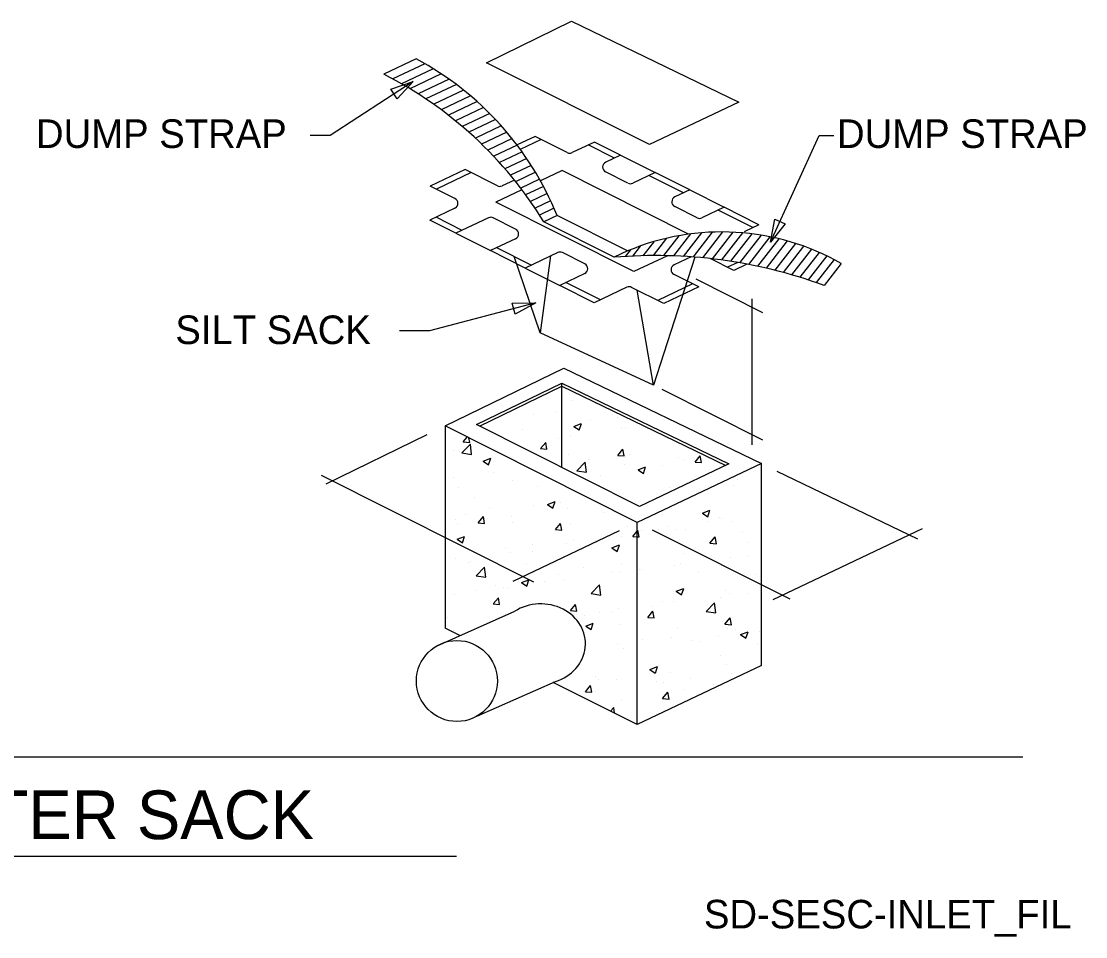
# Model space of a CAD drawing. Extents: x 10109 to 10183.6, y 10015.3 to 10070.3.
# Drawn here: x 10144.72 to 10183.58, y 10015.27 to 10048.68 of the extents above; entities that cross this region are included whole.
import ezdxf

# ---------------------------------------------------------------- set-up
doc = ezdxf.new("R2010")
doc.units = 0
for name, color, linetype in [('Default', 7, 'Continuous'), ('G-ANNO-TEXT', 7, 'Continuous'), ('G-DETL-LINE', 7, 'Continuous'), ('G-DETL-OTLN', 7, 'Continuous'), ('G-DETL-PATT', 7, 'Continuous')]:
    doc.layers.add(name, color=color, linetype=linetype)

# ---------------------------------------------------------------- blocks, each defined once
blk = doc.blocks.new('TERARR')
at = {"layer": 'Default'}
blk.add_lwpolyline([(-0.667, 0.167), (0, 0), (-0.667, -0.167)], close=True, dxfattribs=at)

msp = doc.modelspace()

# ---------------------------------------------------------------- linework, layer by layer
at = {"layer": 'Default'}
for p, q in [((10165.479, 10034.849), (10165.479, 10034.849)), ((10165.702, 10034.715), (10165.702, 10034.715)), ((10164.459, 10032.544), (10164.459, 10032.544)), ((10167.043, 10029.878), (10167.205, 10030.07)), ((10167.205, 10030.07), (10167.233, 10030.103)), ((10167.043, 10029.878), (10167.205, 10029.863)), ((10164.564, 10028.293), (10164.564, 10028.293)), ((10171.674, 10026.421), (10171.674, 10026.421)), ((10165.311, 10026.216), (10165.311, 10026.216)), ((10168.378, 10023.586), (10168.378, 10023.586))]:
    msp.add_line(p, q, dxfattribs=at)
at = {"layer": 'G-ANNO-TEXT'}
for p, q in [((10171.795, 10038.037), (10169.364, 10039.259)), ((10171.408, 10033.218), (10171.408, 10038.547)), ((10163.503, 10038.399), (10159.618, 10037.374)), ((10159.618, 10037.374), (10158.533, 10037.374)), ((10171.795, 10033.388), (10168.12, 10035.235)), ((10155.851, 10031.801), (10159.543, 10033.595)), ((10172.308, 10032.262), (10177.435, 10029.787)), ((10163.427, 10028.205), (10155.687, 10032.094)), ((10166.55, 10030.074), (10162.669, 10028.232)), ((10172.784, 10027.58), (10167.761, 10030.105)), ((10177.609, 10030.155), (10172.153, 10027.567)), ((10129.979, 10018.209), (10160.613, 10018.209))]:
    msp.add_line(p, q, dxfattribs=at)
for points in [[(10159.023, 10046.482), (10156.001, 10044.51), (10155.262, 10044.51)], [(10172.072, 10040.612), (10173.85, 10044.504), (10174.388, 10044.504)]]:
    msp.add_lwpolyline(points, dxfattribs=at)
at = {"layer": 'G-DETL-LINE'}
for p, q in [((10161.704, 10047.166), (10164.813, 10048.676)), ((10164.813, 10048.676), (10170.919, 10045.728)), ((10159.142, 10047.305), (10157.955, 10046.742)), ((10167.65, 10044.177), (10161.704, 10047.166)), ((10170.919, 10045.728), (10167.65, 10044.177)), ((10163.702, 10044.363), (10162.939, 10044.001)), ((10166.373, 10043.684), (10165.42, 10044.163)), ((10161.15, 10043.152), (10159.874, 10042.547)), ((10168.897, 10042.415), (10167.635, 10043.05)), ((10164.281, 10041.586), (10163.795, 10041.355)), ((10166.854, 10040.293), (10164.281, 10041.586)), ((10171.422, 10041.147), (10170.159, 10041.781)), ((10160.815, 10041.047), (10159.863, 10041.526)), ((10166.368, 10040.062), (10163.795, 10041.355)), ((10163.34, 10039.779), (10162.078, 10040.413)), ((10163.666, 10037.309), (10162.717, 10040.092)), ((10164.044, 10040.113), (10163.666, 10037.309)), ((10166.854, 10040.293), (10166.368, 10040.062)), ((10169.309, 10040.069), (10167.799, 10035.397)), ((10170.878, 10039.873), (10170.506, 10039.697)), ((10174.657, 10039.839), (10174.033, 10039.034)), ((10165.864, 10038.51), (10164.602, 10039.145)), ((10167.799, 10035.397), (10167.203, 10038.864)), ((10169.23, 10039.092), (10167.954, 10038.486)), ((10167.799, 10035.397), (10163.666, 10037.309)), ((10161.341, 10033.958), (10164.45, 10035.469)), ((10161.451, 10033.902), (10164.45, 10035.36)), ((10164.45, 10035.36), (10164.45, 10035.469)), ((10164.45, 10035.469), (10170.556, 10032.521)), ((10164.45, 10032.395), (10164.45, 10035.36)), ((10164.45, 10035.36), (10170.442, 10032.467)), ((10167.287, 10030.97), (10161.341, 10033.958)), ((10170.556, 10032.521), (10167.287, 10030.97)), ((10159.901, 10025.888), (10162.736, 10027.142)), ((10161.35, 10023.311), (10164.219, 10024.579)), ((10108.968, 10021.831), (10181.284, 10021.831))]:
    msp.add_line(p, q, dxfattribs=at)
for centre, radius, start, end in [((10153.816, 10037.35), 11.289, 22.0339, 61.8533), ((10151.414, 10033.791), 14.509, 31.4237, 63.2038), ((10170.294, 10032.133), 8.856, 60.4856, 112.8629), ((10167.881, 10022.259), 17.868, 69.8606, 94.8587)]:
    msp.add_arc(centre, radius, start, end, dxfattribs=at)
msp.add_ellipse((10163.686, 10025.957), major_axis=(1.631, 0), ratio=0.894176, start_param=5.045139, end_param=8.475957, dxfattribs=at)
at = {"layer": 'G-DETL-OTLN'}
for p, q in [((10163.479, 10044.475), (10162.819, 10044.162)), ((10164.655, 10043.884), (10163.479, 10044.475)), ((10165.645, 10044.27), (10164.828, 10043.882)), ((10166.598, 10043.791), (10165.645, 10044.27)), ((10166.598, 10043.791), (10166.058, 10043.534)), ((10166.598, 10043.791), (10167.86, 10043.156)), ((10160.927, 10043.264), (10159.651, 10042.659)), ((10162.103, 10042.673), (10160.927, 10043.264)), ((10164.463, 10043.225), (10163.675, 10042.851)), ((10169.081, 10040.905), (10164.463, 10043.225)), ((10166.87, 10042.771), (10166.054, 10043.181)), ((10167.86, 10043.156), (10167.043, 10042.769)), ((10169.122, 10042.522), (10167.86, 10043.156)), ((10162.721, 10042.883), (10162.276, 10042.671)), ((10160.554, 10042.206), (10159.651, 10042.659)), ((10162.996, 10042.529), (10162.04, 10042.076)), ((10169.122, 10042.522), (10168.582, 10042.266)), ((10169.122, 10042.522), (10170.385, 10041.888)), ((10167.086, 10039.54), (10162.04, 10042.076)), ((10160.55, 10041.852), (10159.637, 10041.42)), ((10169.395, 10041.502), (10168.578, 10041.912)), ((10170.385, 10041.888), (10169.567, 10041.5)), ((10171.647, 10041.253), (10170.385, 10041.888)), ((10160.59, 10040.941), (10159.637, 10041.42)), ((10161.779, 10041.505), (10160.59, 10040.941)), ((10162.769, 10041.092), (10161.952, 10041.503)), ((10171.647, 10041.253), (10171.107, 10040.997)), ((10160.59, 10040.941), (10161.852, 10040.306)), ((10162.765, 10040.739), (10161.852, 10040.306)), ((10163.115, 10039.672), (10161.852, 10040.306)), ((10164.304, 10040.236), (10163.115, 10039.672)), ((10165.293, 10039.824), (10164.476, 10040.234)), ((10168.312, 10040.121), (10167.086, 10039.54)), ((10169.173, 10040.08), (10168.555, 10039.787)), ((10170.729, 10039.585), (10169.873, 10040.015)), ((10163.115, 10039.672), (10164.377, 10039.038)), ((10171.21, 10039.814), (10170.729, 10039.585)), ((10165.289, 10039.47), (10164.377, 10039.038)), ((10169.453, 10038.98), (10168.551, 10039.433)), ((10165.639, 10038.403), (10164.377, 10039.038)), ((10166.828, 10038.968), (10165.639, 10038.403)), ((10168.177, 10038.375), (10167.001, 10038.966)), ((10169.453, 10038.98), (10168.177, 10038.375)), ((10160.19, 10033.909), (10164.529, 10036.018)), ((10164.529, 10036.018), (10171.74, 10032.536)), ((10160.19, 10033.909), (10160.19, 10026.532)), ((10167.205, 10030.384), (10160.19, 10033.909)), ((10171.74, 10032.536), (10167.205, 10030.384)), ((10171.74, 10025.159), (10171.74, 10032.536)), ((10167.205, 10023.007), (10167.205, 10030.384)), ((10160.736, 10026.258), (10160.19, 10026.532)), ((10171.74, 10025.159), (10167.205, 10023.007)), ((10167.205, 10023.007), (10164.143, 10024.546))]:
    msp.add_line(p, q, dxfattribs=at)
msp.add_circle((10160.625, 10024.599), 1.478, dxfattribs=at)
for centre, start, end in [((10164.744, 10044.06), 243.3185, 295.3798), ((10166.142, 10043.357), 115.3798, 243.3185), ((10166.959, 10042.946), 243.3185, 295.3798), ((10162.192, 10042.849), 243.3185, 295.3798), ((10160.465, 10042.03), 295.3798, 63.3185), ((10168.666, 10042.088), 115.3798, 243.3185), ((10161.864, 10041.327), 63.3185, 115.3798), ((10169.483, 10041.678), 243.3185, 295.3798), ((10162.68, 10040.917), 295.3798, 63.3185), ((10164.388, 10040.059), 63.3185, 115.3798), ((10165.205, 10039.648), 295.3798, 63.3185), ((10168.639, 10039.609), 115.3798, 243.3185), ((10166.913, 10038.79), 63.3185, 115.3798)]:
    msp.add_arc(centre, 0.197, start, end, dxfattribs=at)
at = {"layer": 'G-DETL-PATT'}
for p, q in [((10159.459, 10047.129), (10158.283, 10046.571)), ((10159.763, 10046.947), (10158.6, 10046.395)), ((10160.056, 10046.759), (10158.908, 10046.215)), ((10160.337, 10046.566), (10159.206, 10046.03)), ((10160.608, 10046.368), (10159.496, 10045.841)), ((10160.869, 10046.166), (10159.777, 10045.647)), ((10161.12, 10045.958), (10160.049, 10045.45)), ((10161.363, 10045.747), (10160.314, 10045.249)), ((10161.596, 10045.531), (10160.571, 10045.045)), ((10161.821, 10045.311), (10160.821, 10044.837)), ((10162.037, 10045.088), (10161.064, 10044.626)), ((10162.246, 10044.86), (10161.299, 10044.411)), ((10162.446, 10044.629), (10161.528, 10044.193)), ((10162.639, 10044.394), (10161.751, 10043.972)), ((10162.824, 10044.155), (10161.967, 10043.749)), ((10163.002, 10043.913), (10162.176, 10043.522)), ((10163.172, 10043.668), (10162.38, 10043.292)), ((10163.336, 10043.419), (10162.577, 10043.059)), ((10163.492, 10043.167), (10162.769, 10042.823)), ((10163.641, 10042.911), (10162.954, 10042.585)), ((10163.783, 10042.652), (10163.134, 10042.344)), ((10163.918, 10042.39), (10163.308, 10042.1)), ((10164.047, 10042.124), (10163.477, 10041.854)), ((10164.168, 10041.855), (10163.639, 10041.604)), ((10168.724, 10040.848), (10168.163, 10040.124)), ((10169.148, 10040.914), (10168.529, 10040.115)), ((10169.555, 10040.958), (10168.889, 10040.098)), ((10169.946, 10040.982), (10169.244, 10040.074)), ((10170.325, 10040.988), (10169.594, 10040.044)), ((10170.691, 10040.98), (10169.938, 10040.008)), ((10171.046, 10040.956), (10170.278, 10039.965)), ((10171.391, 10040.92), (10170.614, 10039.916)), ((10171.727, 10040.872), (10170.944, 10039.862)), ((10172.053, 10040.812), (10171.271, 10039.802)), ((10167.314, 10040.472), (10167.031, 10040.106)), ((10167.812, 10040.633), (10167.414, 10040.12)), ((10168.28, 10040.756), (10167.792, 10040.126)), ((10172.372, 10040.741), (10171.593, 10039.737)), ((10172.682, 10040.661), (10171.912, 10039.666)), ((10172.985, 10040.57), (10172.226, 10039.59)), ((10173.28, 10040.47), (10172.536, 10039.509)), ((10166.961, 10040.337), (10166.771, 10040.092)), ((10173.569, 10040.361), (10172.843, 10039.424)), ((10173.851, 10040.243), (10173.146, 10039.333)), ((10174.126, 10040.117), (10173.445, 10039.238)), ((10174.394, 10039.982), (10173.741, 10039.138)), ((10164.803, 10034.838), (10164.803, 10034.838)), ((10163.408, 10034.322), (10163.408, 10034.322)), ((10164.209, 10034.41), (10164.209, 10034.41)), ((10166.308, 10034.321), (10166.308, 10034.321)), ((10166.478, 10034.225), (10166.478, 10034.225)), ((10164.891, 10033.892), (10165.166, 10033.997)), ((10164.891, 10033.892), (10165.087, 10033.76)), ((10165.087, 10033.759), (10165.167, 10033.997)), ((10165.493, 10034.095), (10165.493, 10034.095)), ((10166.644, 10033.852), (10166.644, 10033.852)), ((10166.774, 10033.806), (10166.774, 10033.806)), ((10160.536, 10033.442), (10160.536, 10033.442)), ((10160.857, 10033.329), (10161.002, 10033.502)), ((10161.092, 10033.308), (10161.062, 10033.471)), ((10163.01, 10033.768), (10163.01, 10033.768)), ((10164.351, 10033.458), (10164.351, 10033.458)), ((10164.755, 10033.529), (10164.755, 10033.529)), ((10160.499, 10033.028), (10160.499, 10033.028)), ((10160.809, 10032.921), (10161.116, 10033.24)), ((10160.857, 10033.329), (10161.092, 10033.308)), ((10161.159, 10032.867), (10161.116, 10033.24)), ((10163.677, 10033.082), (10163.867, 10033.308)), ((10163.677, 10033.082), (10163.912, 10033.061)), ((10163.912, 10033.061), (10163.867, 10033.308)), ((10166.497, 10032.835), (10166.687, 10033.061)), ((10166.733, 10032.814), (10166.687, 10033.061)), ((10160.727, 10032.982), (10160.727, 10032.982)), ((10160.809, 10032.921), (10161.159, 10032.867)), ((10161.587, 10032.623), (10161.863, 10032.729)), ((10161.587, 10032.623), (10161.783, 10032.491)), ((10161.783, 10032.491), (10161.863, 10032.729)), ((10164.697, 10032.851), (10164.697, 10032.851)), ((10165.443, 10032.674), (10165.443, 10032.674)), ((10166.497, 10032.835), (10166.732, 10032.815)), ((10166.796, 10032.762), (10166.796, 10032.762)), ((10166.933, 10032.87), (10166.933, 10032.87)), ((10168.713, 10032.748), (10168.713, 10032.748)), ((10168.895, 10032.673), (10168.895, 10032.673)), ((10169.318, 10032.588), (10169.507, 10032.814)), ((10169.553, 10032.568), (10169.507, 10032.814)), ((10165.006, 10032.27), (10165.312, 10032.589)), ((10165.006, 10032.27), (10165.356, 10032.216)), ((10165.356, 10032.216), (10165.312, 10032.589)), ((10166.726, 10032.497), (10166.726, 10032.497)), ((10167.238, 10032.308), (10167.514, 10032.414)), ((10167.238, 10032.308), (10167.434, 10032.176)), ((10167.434, 10032.176), (10167.514, 10032.414)), ((10168.146, 10032.476), (10168.146, 10032.476)), ((10169.318, 10032.588), (10169.553, 10032.568)), ((10160.486, 10032.021), (10160.486, 10032.021)), ((10161.976, 10032.217), (10161.976, 10032.217)), ((10162.665, 10031.925), (10162.665, 10031.925)), ((10165.852, 10032.082), (10165.852, 10032.082)), ((10170.855, 10031.971), (10170.855, 10031.971)), ((10160.679, 10031.673), (10160.679, 10031.673)), ((10163.559, 10031.689), (10163.559, 10031.689)), ((10168.381, 10031.646), (10168.381, 10031.646)), ((10170.707, 10031.734), (10170.707, 10031.734)), ((10161.266, 10031.295), (10161.266, 10031.295)), ((10163.934, 10031.04), (10164.21, 10031.146)), ((10164.13, 10030.908), (10164.21, 10031.146)), ((10164.409, 10031.123), (10164.409, 10031.123)), ((10161.832, 10030.93), (10161.832, 10030.93)), ((10163.424, 10030.993), (10163.424, 10030.993)), ((10163.931, 10030.841), (10163.931, 10030.841)), ((10163.934, 10031.04), (10164.13, 10030.908)), ((10164.66, 10030.911), (10164.66, 10030.911)), ((10166.03, 10030.753), (10166.03, 10030.753)), ((10169.585, 10030.725), (10169.861, 10030.831)), ((10169.585, 10030.725), (10169.781, 10030.593)), ((10169.781, 10030.593), (10169.861, 10030.831)), ((10160.562, 10030.49), (10160.562, 10030.49)), ((10160.631, 10030.364), (10160.631, 10030.364)), ((10160.941, 10030.666), (10160.941, 10030.666)), ((10161.402, 10030.371), (10161.592, 10030.597)), ((10161.402, 10030.371), (10161.637, 10030.35)), ((10161.637, 10030.35), (10161.592, 10030.597)), ((10162.617, 10030.616), (10162.617, 10030.616)), ((10162.661, 10030.402), (10162.661, 10030.402)), ((10164.223, 10030.124), (10164.412, 10030.35)), ((10164.458, 10030.103), (10164.412, 10030.35)), ((10164.76, 10030.313), (10164.76, 10030.313)), ((10168.129, 10030.664), (10168.129, 10030.664)), ((10169.821, 10030.421), (10169.821, 10030.421)), ((10170.228, 10030.575), (10170.228, 10030.575)), ((10170.276, 10030.523), (10170.276, 10030.523)), ((10170.659, 10030.425), (10170.659, 10030.425)), ((10164.223, 10030.124), (10164.458, 10030.104)), ((10166.859, 10030.224), (10166.859, 10030.224)), ((10167.278, 10029.857), (10167.233, 10030.103)), ((10167.347, 10030.095), (10167.347, 10030.095)), ((10167.983, 10030.13), (10167.983, 10030.13)), ((10168.331, 10030.225), (10168.331, 10030.225)), ((10168.617, 10030.13), (10168.617, 10030.13)), ((10168.958, 10030.136), (10168.958, 10030.136)), ((10171.057, 10030.047), (10171.057, 10030.047)), ((10160.631, 10029.772), (10160.906, 10029.878)), ((10160.631, 10029.772), (10160.826, 10029.64)), ((10160.826, 10029.64), (10160.906, 10029.877)), ((10163.374, 10029.572), (10163.374, 10029.572)), ((10164.612, 10029.602), (10164.612, 10029.602)), ((10164.864, 10029.768), (10164.864, 10029.768)), ((10165.69, 10029.736), (10165.69, 10029.736)), ((10166.282, 10029.457), (10166.557, 10029.563)), ((10166.477, 10029.325), (10166.557, 10029.562)), ((10166.631, 10029.879), (10166.631, 10029.879)), ((10167.205, 10029.863), (10167.278, 10029.857)), ((10169.863, 10029.631), (10170.053, 10029.857)), ((10169.863, 10029.631), (10170.098, 10029.61)), ((10170.099, 10029.61), (10170.053, 10029.856)), ((10171.219, 10029.66), (10171.219, 10029.66)), ((10162.39, 10029.442), (10162.39, 10029.442)), ((10162.57, 10029.307), (10162.57, 10029.307)), ((10163.397, 10029.342), (10163.397, 10029.342)), ((10166.282, 10029.457), (10166.477, 10029.325)), ((10168.925, 10029.266), (10168.925, 10029.266)), ((10171.27, 10029.197), (10171.27, 10029.197)), ((10160.583, 10029.055), (10160.583, 10029.055)), ((10161.05, 10028.931), (10161.05, 10028.931)), ((10161.104, 10028.949), (10161.104, 10028.949)), ((10161.331, 10028.44), (10161.637, 10028.759)), ((10161.681, 10028.385), (10161.637, 10028.759)), ((10163.149, 10028.843), (10163.149, 10028.843)), ((10165.248, 10028.754), (10165.248, 10028.754)), ((10166.632, 10028.873), (10166.632, 10028.873)), ((10168.569, 10028.821), (10168.569, 10028.821)), ((10168.786, 10028.87), (10168.786, 10028.87)), ((10170.611, 10029.116), (10170.611, 10029.116)), ((10161.331, 10028.44), (10161.68, 10028.386)), ((10164.339, 10028.479), (10164.339, 10028.479)), ((10166.313, 10028.544), (10166.313, 10028.544)), ((10166.583, 10028.57), (10166.583, 10028.57)), ((10167.297, 10028.674), (10167.297, 10028.674)), ((10167.347, 10028.665), (10167.347, 10028.665)), ((10169.446, 10028.576), (10169.446, 10028.576)), ((10171.545, 10028.488), (10171.545, 10028.488)), ((10162.046, 10028.085), (10162.046, 10028.085)), ((10162.34, 10028.021), (10162.34, 10028.021)), ((10162.522, 10027.998), (10162.522, 10027.998)), ((10162.978, 10028.189), (10163.253, 10028.294)), ((10162.978, 10028.189), (10163.173, 10028.057)), ((10163.173, 10028.057), (10163.253, 10028.294)), ((10163.829, 10028.217), (10163.829, 10028.217)), ((10165.527, 10027.789), (10165.834, 10028.108)), ((10165.877, 10027.735), (10165.834, 10028.108)), ((10168.629, 10027.874), (10168.904, 10027.98)), ((10168.824, 10027.742), (10168.904, 10027.979)), ((10160.536, 10027.746), (10160.536, 10027.746)), ((10161.356, 10027.891), (10161.356, 10027.891)), ((10161.948, 10027.413), (10162.137, 10027.639)), ((10162.183, 10027.392), (10162.138, 10027.639)), ((10165.527, 10027.789), (10165.877, 10027.735)), ((10168.629, 10027.874), (10168.824, 10027.742)), ((10170.235, 10027.646), (10170.235, 10027.646)), ((10170.427, 10027.89), (10170.427, 10027.89)), ((10170.564, 10027.807), (10170.564, 10027.807)), ((10171.219, 10027.775), (10171.219, 10027.775)), ((10161.948, 10027.413), (10162.183, 10027.393)), ((10164.768, 10027.167), (10164.958, 10027.392)), ((10165.003, 10027.146), (10164.958, 10027.392)), ((10166.535, 10027.261), (10166.535, 10027.261)), ((10167.752, 10027.319), (10167.752, 10027.319)), ((10168.134, 10027.497), (10168.134, 10027.497)), ((10168.521, 10027.512), (10168.521, 10027.512)), ((10169.724, 10027.138), (10170.03, 10027.457)), ((10170.074, 10027.084), (10170.03, 10027.457)), ((10160.284, 10026.922), (10160.284, 10026.922)), ((10164.768, 10027.167), (10165.003, 10027.146)), ((10165.278, 10026.993), (10165.278, 10026.993)), ((10165.841, 10027.103), (10165.841, 10027.103)), ((10166.263, 10027.123), (10166.263, 10027.123)), ((10167.589, 10026.92), (10167.778, 10027.146)), ((10167.589, 10026.92), (10167.824, 10026.899)), ((10167.824, 10026.899), (10167.778, 10027.145)), ((10169.724, 10027.138), (10170.074, 10027.084)), ((10170.409, 10026.673), (10170.599, 10026.899)), ((10170.644, 10026.652), (10170.599, 10026.899)), ((10160.488, 10026.437), (10160.488, 10026.437)), ((10165.325, 10026.606), (10165.6, 10026.711)), ((10165.325, 10026.606), (10165.52, 10026.474)), ((10165.52, 10026.473), (10165.6, 10026.711)), ((10166.581, 10026.656), (10166.581, 10026.656)), ((10168.68, 10026.567), (10168.68, 10026.567)), ((10170.409, 10026.673), (10170.644, 10026.652)), ((10170.516, 10026.498), (10170.516, 10026.498)), ((10170.779, 10026.478), (10170.779, 10026.478)), ((10167.41, 10026.128), (10167.41, 10026.128)), ((10168.473, 10026.204), (10168.473, 10026.204)), ((10169.201, 10026.095), (10169.201, 10026.095)), ((10169.509, 10026.039), (10169.509, 10026.039)), ((10170.185, 10026.224), (10170.185, 10026.224)), ((10170.976, 10026.291), (10171.251, 10026.396)), ((10170.976, 10026.291), (10171.171, 10026.159)), ((10171.171, 10026.158), (10171.251, 10026.396)), ((10166.487, 10025.952), (10166.487, 10025.952)), ((10166.717, 10025.768), (10166.717, 10025.768)), ((10171.608, 10025.95), (10171.608, 10025.95)), ((10170.265, 10025.544), (10170.265, 10025.544)), ((10167.672, 10025.022), (10167.947, 10025.128)), ((10167.672, 10025.022), (10167.867, 10024.891)), ((10167.868, 10024.89), (10167.947, 10025.128)), ((10167.972, 10025.15), (10167.972, 10025.15)), ((10168.426, 10024.895), (10168.426, 10024.895)), ((10170.468, 10025.189), (10170.468, 10025.189)), ((10170.64, 10024.87), (10170.64, 10024.87)), ((10165.678, 10024.757), (10165.678, 10024.757)), ((10165.799, 10024.657), (10165.799, 10024.657)), ((10166.44, 10024.643), (10166.44, 10024.643)), ((10167.898, 10024.568), (10167.898, 10024.568)), ((10168.166, 10024.544), (10168.166, 10024.544)), ((10169.151, 10024.674), (10169.151, 10024.674)), ((10169.997, 10024.48), (10169.997, 10024.48)), ((10165.314, 10024.209), (10165.503, 10024.435)), ((10165.314, 10024.209), (10165.549, 10024.188)), ((10165.549, 10024.188), (10165.503, 10024.434)), ((10165.683, 10024.217), (10165.683, 10024.217)), ((10168.134, 10023.962), (10168.324, 10024.188)), ((10168.369, 10023.941), (10168.324, 10024.188)), ((10168.914, 10024.287), (10168.914, 10024.287)), ((10166.621, 10023.893), (10166.621, 10023.893)), ((10168.134, 10023.962), (10168.369, 10023.941)), ((10166.23, 10023.497), (10166.355, 10023.627)), ((10166.379, 10023.422), (10166.355, 10023.627))]:
    msp.add_line(p, q, dxfattribs=at)

# ---------------------------------------------------------------- block references
at = {"layer": 'G-ANNO-TEXT', "yscale": 1.24992}
for p, xscale, rotation in [((10159.023, 10046.482), 1.24992, 33.111690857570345), ((10172.072, 10040.612), 1.2499200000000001, -114.56063597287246), ((10163.503, 10038.399), 1.2499200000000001, 14.784830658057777)]:
    msp.add_blockref('TERARR', p, dxfattribs=dict(at, xscale=xscale, rotation=rotation))

# ---------------------------------------------------------------- texts
at = {"layer": 'G-ANNO-TEXT'}
for s, height, p in [('DUMP STRAP', 1.044, (10145.26, 10044.053)), ('DUMP STRAP', 1.044, (10174.499, 10044.053)), ('SILT SACK', 1.044, (10150.346, 10036.895)), ('INLET FILTER SACK', 1.776, (10132.71, 10018.828)), ('SD-SESC-INLET_FIL', 1.044, (10169.642, 10015.568))]:
    msp.add_text(s, height=height, dxfattribs=at).set_placement(p)

doc.saveas('drawing.dxf')
